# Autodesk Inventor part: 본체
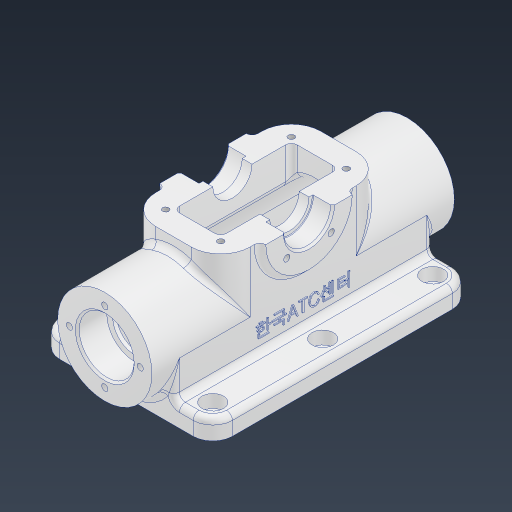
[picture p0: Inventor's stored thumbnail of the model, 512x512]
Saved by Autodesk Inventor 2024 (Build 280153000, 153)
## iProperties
Created: 2024-06
Part Number: 본체
Material: 알루미늄 6061
Document SubType Name: Modeling
Designer: kh_501
Density: 2.7 g/cm^3
Appearance: 알루미늄 - 평지
Mass: 551.548 g
Surface Area: 612.261 cm^2
Volume: 204.277 cm^3
Author: kh_501
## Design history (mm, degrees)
sketch "스케치1"
  geometry: L1 (-44, 66)-(44, 66); L2 (44, 66)-(44, -66); L3 (44, -66)-(-44, -66); L4 (-44, -66)-(-44, 66); L5 (-44, 66)-(44, -66); L6 (44, 66)-(-44, -66); 1 further point
  constraints: 12 end point, 2 midpoint, 2 parallel, 1 horizontal, 1 perpendicular
  dimensions: "d0" = 132 distance of L1.end L2.end; "d1" = 88 distance of L1.start L1.end
extrude "돌출1" new body sketch "스케치1" distance "d2" = 10; taper "d3" = 0 deg
sketch "스케치2"
  geometry: L1 (28, 77)-(4, 77); L2 (4, 77)-(4, -77); L3 (4, -77)-(28, -77); L4 (28, -77)-(28, 77); L5 (0, 66)-(0, -66) reference; 3 further points
  constraints: 8 end point, 2 midpoint, 2 parallel, 1 horizontal, 1 horizontal alignment, 1 perpendicular
  dimensions: "d4" = 28 distance between parallel lines of L4 L5; "d5" = 48 diameter of L2 L4; "d6" = 154 distance of L3.end L1.start
revolve "회전1" sketch "스케치2" stored, may be unused: angle "d7" = 90 deg
sketch "스케치4"
  geometry: L1 (-44, -66)-(44, -66) reference; L2 (24, 66)-(-24, 66); L3 (-24, 66)-(-24, -66); L4 (-24, -66)-(24, -66); L5 (24, -66)-(24, 66); L6 (24, 66)-(-24, -66); L7 (-24, 66)-(24, -66); 2 further points
  constraints: 12 end point, 2 midpoint, 2 parallel, 1 horizontal, 1 perpendicular, 1 point on line
  dimensions: "d11" = 48 distance between parallel lines of L5 L3
extrude "돌출2" join sketch "스케치4" stored distance "d12" = 10; taper "d13" = 0 deg
node "작업 평면1"
sketch "스케치3"
  geometry: L1 (-24, 42)-(24, 42); L2 (24, 42)-(24, -42); L3 (24, -42)-(-24, -42); L4 (-24, -42)-(-24, 42); L5 (-24, 42)-(24, -42); L6 (24, 42)-(-24, -42); 1 further point
  constraints: 12 end point, 2 midpoint, 2 parallel, 1 horizontal, 1 perpendicular
  dimensions: "d9" = 84 distance of L1.end L2.end; "d10" = 48 distance of L1.start L1.end
extrude "돌출3" join sketch "스케치3" stored distance "d14" = 10; taper "d15" = 0 deg
sketch "스케치5"
  geometry: C1 r 24 at (0, 0) reference; 2 further points
  constraints: 1 coincident
hole "구멍1" sketch "스케치5" at (0, 0) diameter "d16" = 22; stored, may be unused: countersink angle "d20" = 90 deg, drill point angle "d22" = 118 deg; dims "d17" = 20, "d18" = 28, "d19" = 15, "d21" = 23
sketch "스케치6"
  geometry: C1 r 24 at (0, 0) reference; 2 further points
  constraints: 1 coincident
hole "구멍2" sketch "스케치6" at (0, 0) diameter "d23" = 22; stored, may be unused: countersink angle "d27" = 90 deg, drill point angle "d29" = 118 deg; dims "d24" = 6, "d25" = 28, "d26" = 15, "d28" = 8
sketch "스케치8"
  geometry: L1 (0, 28)-(0, 0); L2 (18, 28)-(18, 0); L3 (-18, 0)-(-18, 28); L4 (24, 10)-(24, 28) reference; C1 r 11 at (0, 28) reference; A1 r 18 centre (0, 28) between (18, 28) and (-18, 28); A2 r 18 centre (0, 0) between (-18, 0) and (18, 0); 1 further point
  constraints: 8 end point, 4 point on circle, 4 tangent, 2 centre point, 1 midpoint, 1 parallel, 1 vertical
  dimensions: "d30" = 6 distance between parallel lines of L2 L4
extrude "돌출4" cut sketch "스케치8" stored distance "d31" = 120; taper "d32" = 0 deg
sketch "스케치10"
  geometry: L1 (24, 49)-(108, 49) reference; C1 r 22 at (66, 49); 3 further points
  constraints: 1 centre point, 1 midpoint
  dimensions: "d33" = 44 diameter of C1
extrude "돌출5" join sketch "스케치10" distance "d34" = 3; taper "d35" = 0 deg
sketch "스케치11"
  geometry: A1 r 22 centre (66, 49) between (44, 49) and (88, 49) reference; 2 further points
  constraints: 1 coincident
hole "구멍3" sketch "스케치11" at (66, 49) diameter "d36" = 20; stored, may be unused: countersink angle "d40" = 90 deg, drill point angle "d42" = 118 deg; dims "d37" = 6, "d38" = 24, "d39" = 10, "d41" = 8
sketch "스케치12"
  geometry: L1 (66, 49)-(54.686, 37.686); L2 (66, 49)-(77.314, 37.686); L3 (66, 49)-(66, 65); A1 r 10 centre (66, 49) between (56, 49) and (76, 49) reference; A2 r 16 centre (66, 49) between (54.686, 37.686) and (77.314, 37.686); 3 further points
  constraints: 6 end point, 3 coincident, 3 point on circle, 1 centre point, 1 perpendicular, 1 vertical, 1 other
  dimensions: "d43" = 32 diameter of A2
hole "구멍4" sketch "스케치12" at (54.686, 37.686), (77.314, 37.686) diameter "d44" = 3.242; stored, may be unused: countersink angle "d48" = 90 deg, drill point angle "d50" = 118 deg; dims "d45" = 8, "d46" = 24, "d47" = 10, "d49" = 10
sketch "스케치13"
  geometry: L1 (12, -30)-(-12, -30); L2 (-12, -30)-(-12, 30); L3 (-12, 30)-(12, 30); L4 (12, 30)-(12, -30); L5 (12, -30)-(-12, 30); L6 (-12, -30)-(12, 30); 1 further point
  constraints: 12 end point, 2 midpoint, 2 parallel, 1 horizontal, 1 perpendicular
  dimensions: "d51" = 60 distance of L1.end L2.end; "d52" = 24 distance of L2.end L3.end
extrude "돌출6" cut sketch "스케치13" extent not by distance; stored distance "d53" = 0; taper "d54" = 0 deg
sketch "스케치14" dims "d55" = 36
  geometry: C1 r 11 at (0, 0) reference; 3 further points
  constraints: 1 coincident, 1 vertical alignment, 2 other
hole "구멍5" sketch "스케치14" at (0, 18) diameter "d56" = 3.242; stored, may be unused: countersink angle "d60" = 90 deg, drill point angle "d62" = 118 deg; dims "d57" = 8, "d58" = 4, "d59" = 2, "d61" = 10
fillet "모깎기15" dims "d104" = 3
fillet "모깎기17" dims "d106" = 3
fillet "모깎기2" dims "d69" = 3
chamfer "모따기1" distance "d70" = 1; stored, may be unused: second distance "d71" = 2, angle "d72" = 45 deg
fillet "모깎기3" dims "d73" = 0.3
sketch "스케치15"
  geometry: L1 (-14, 32)-(14, 32); L2 (14, 32)-(14, -32); L3 (14, -32)-(-14, -32); L4 (-14, -32)-(-14, 32); L5 (-14, 32)-(14, -32); L6 (14, 32)-(-14, -32); 5 further points
  constraints: 12 end point, 4 coincident, 2 midpoint, 2 parallel, 1 horizontal, 1 perpendicular
  dimensions: "d66" = 64 distance of L1.end L2.end; "d67" = 28 distance of L2.end L3.end
hole "구멍6" sketch "스케치15" at (14, 32), (14, -32), (-14, -32), (-14, 32) diameter "d74" = 3.242; stored, may be unused: countersink angle "d78" = 90 deg, drill point angle "d80" = 118 deg; dims "d75" = 8, "d76" = 4, "d77" = 2, "d79" = 10
fillet "모깎기4" dims "d81" = 15
fillet "모깎기5" dims "d82" = 3
sketch "스케치16"
  geometry: L1 (-34, 56)-(34, 56); L2 (34, 56)-(34, -56); L3 (34, -56)-(-34, -56); L4 (-34, -56)-(-34, 56); L5 (-34, 56)-(34, -56); L6 (34, 56)-(-34, -56); 7 further points
  constraints: 12 end point, 4 coincident, 4 midpoint, 2 parallel, 1 horizontal, 1 perpendicular
  dimensions: "d83" = 112 distance of L1.end L2.end; "d84" = 68 distance of L1.start L1.end
hole "구멍7" sketch "스케치16" at (34, 56), (34, -56), (-34, -56), (-34, 56), (34, 0), (-34, 0) diameter "d85" = 6.6; stored, may be unused: countersink angle "d89" = 90 deg, drill point angle "d91" = 118 deg; dims "d86" = 8, "d87" = 11, "d88" = 6.6, "d90" = 10
fillet "모깎기6" dims "d92" = 10
fillet "모깎기12" dims "d98" = 3
fillet "모깎기13" dims "d99" = 3
fillet "모깎기14" dims "d100" = 3
sketch "스케치17"
  geometry: L1 (-29, -28)-(83, -28) reference; 3 further points
  constraints: 1 midpoint, 1 vertical alignment, 1 other
  dimensions: "d101" = 20 distance from line of point (27, -8) L1
feature "엠보싱1" sketch "스케치17" dims "d0" = 132, "d1" = 88, "d9" = 84, "d10" = 48, "d102" = 0.5, "d103" = 0
node "솔리드1"
mirror "미러1"
pattern_circular "원형 패턴1" dims angle "d64" = 360 deg
mirror "미러2"
feature "A9D066F2-1C7D-4E18-AEED-F7BC21143FA4" dims "d16" = 22, "d17" = 20, "d18" = 28, "d19" = 15, "d20" = 90 deg, "d21" = 23, "d22" = 118 deg
other parameters: "d8" = 59
